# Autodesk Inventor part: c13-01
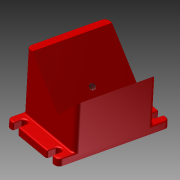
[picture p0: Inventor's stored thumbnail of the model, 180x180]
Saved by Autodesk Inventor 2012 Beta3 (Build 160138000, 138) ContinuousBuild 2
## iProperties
Created: 2010-11
Part Number: c13-01
Material: Default
Document SubType Name: Modeling
Designer: Beta-8540w
Density: 1 g/cm^3
Author: Beta-8540w
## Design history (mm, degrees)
sketch "Sketch1"
  geometry: L1 (-45, 0)-(45, 0); L2 (45, 0)-(45, 10); L3 (45, 10)-(-45, 10); L4 (-45, 10)-(-45, 0); L5 (-45, 10)-(-45, 90); L6 (-45, 90)-(-35, 90); L7 (-35, 90)-(14.497, 40.503); L8 (14.497, 40.503)-(45, 71.005); L9 (45, 71.005)-(45, 10); 2 further points
  constraints: 18 end point, 4 perpendicular, 3 collinear, 2 parallel, 2 point on line, 1 coincident, 1 horizontal, 1 midpoint
  dimensions: "d0" = 90 distance of L3.end L2.end; "d1" = 10 distance of L2.end L1.end; "d2" = 80 distance of L5.start L5.end; "d3" = 10 distance of L5.end L6.end; "d4" = 70 distance of L6.end L7.end; "d5" = 135 deg angle of L6 L7
extrude "Extrusion1" new body sketch "Sketch1" stored distance "d8" = 100; taper "d9" = 0 deg
extrude "Extrusion2" join sketch "Sketch1" stored distance "d10" = 140; taper "d11" = 0 deg
fillet "Fillet1" dims "d12" = 6
fillet "Fillet2" dims "d13" = 2
sketch "Sketch2"
  geometry: L1 (78, -2)-(0, -2) reference; L2 (-6, 4)-(-6, 132) reference; L3 (4.5, -2)-(13.5, -2); L4 (13.5, -2)-(13.5, 8); L5 (13.5, 8)-(4.5, 8); L6 (4.5, 8)-(4.5, -2); 2 further points
  constraints: 8 end point, 2 parallel, 1 horizontal, 1 horizontal alignment, 1 midpoint, 1 perpendicular, 1 point on line, 2 other
  dimensions: "d14" = 9 distance of L5.end L4.end; "d15" = 10 distance of L4.end L3.end; "d16" = 15 distance from line of point (9, 8) L2
extrude "Extrusion3" cut sketch "Sketch2" stored distance "d17" = 140; taper "d18" = 0 deg
mirror "Mirror1"
mirror "Mirror2"
fillet "Fillet3" dims "d28" = 2
hole "Hole1" diameter "d21" = 8.376; stored, may be unused: countersink angle "d25" = 90 deg, drill point angle "d27" = 118 deg; dims "d19" = 50, "d20" = 15, "d22" = 30, "d23" = 4, "d24" = 2, "d26" = 33.5
body "Solid1"
